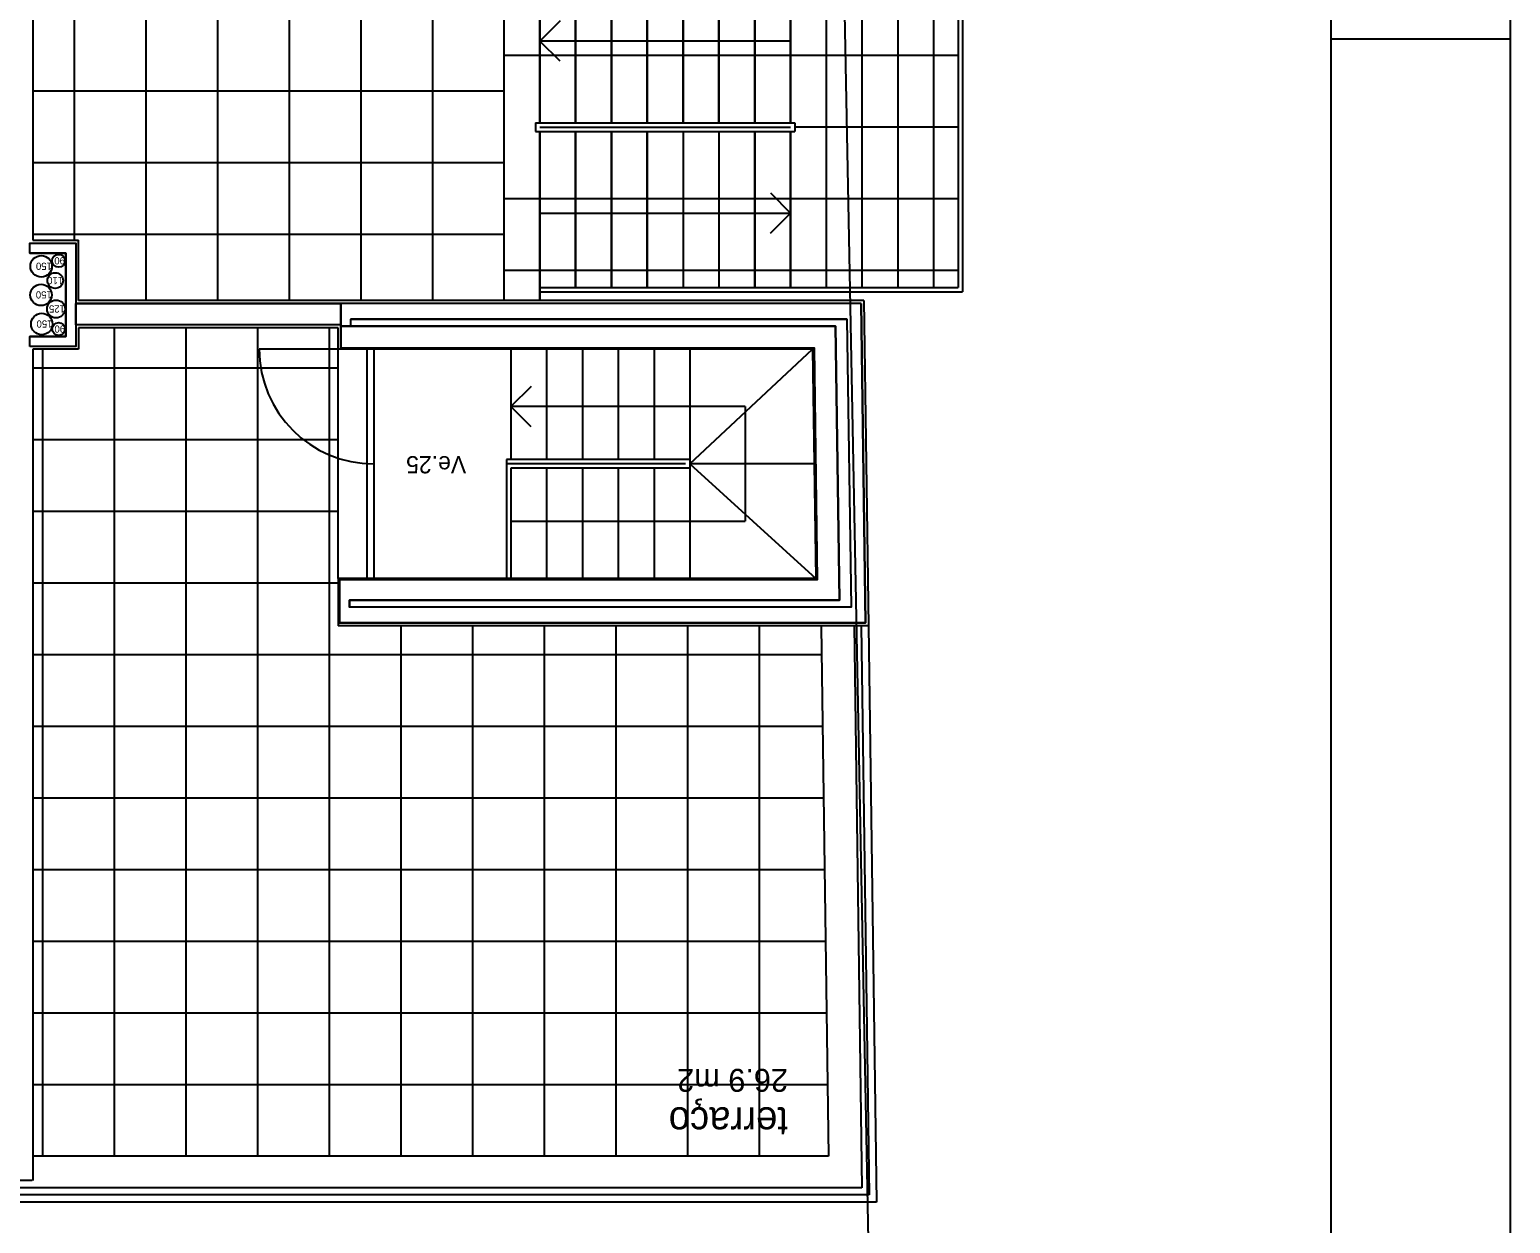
# Model space of a CAD drawing. Extents: x 1278 to 1356, y -253.7 to -224.
# Drawn here: x 1345.63 to 1355.97, y -247.07 to -238.74 of the extents above; entities that cross this region are included whole.
import ezdxf

# ---------------------------------------------------------------- set-up
doc = ezdxf.new("R2010")
doc.units = 0
for name, color, linetype in [('corte', 7, 'Continuous'), ('estereoctomias', 7, 'Continuous'), ('estrutura-eixos', 7, 'Continuous'), ('Level 1', 7, 'Continuous'), ('Level 10', 7, 'Continuous'), ('Level 13', 7, 'Continuous'), ('Level 2', 7, 'Continuous'), ('Level 21', 7, 'Continuous'), ('Level 40', 7, 'Continuous'), ('Level 41', 7, 'Continuous'), ('Level 60', 7, 'Continuous'), ('Level 62', 7, 'Continuous'), ('portas', 7, 'Continuous'), ('revestimentos', 7, 'Continuous')]:
    doc.layers.add(name, color=color, linetype=linetype)

msp = doc.modelspace()

# ---------------------------------------------------------------- linework, layer by layer
at = {"layer": 'corte'}
for p, q in [((1345.634, -240.234), (1345.954, -240.234)), ((1345.954, -240.234), (1345.954, -240.954)), ((1345.634, -240.304), (1345.884, -240.304)), ((1345.884, -240.304), (1345.884, -240.884)), ((1351.435, -240.654), (1345.954, -240.654)), ((1351.435, -240.654), (1351.466, -242.884)), ((1351.336, -240.764), (1347.875, -240.764)), ((1345.884, -240.884), (1345.634, -240.884)), ((1347.805, -240.804), (1345.954, -240.804)), ((1345.954, -240.954), (1345.634, -240.954))]:
    msp.add_line(p, q, dxfattribs=at)
at = {"layer": 'estereoctomias'}
msp.add_line((1348.943, -240.634), (1348.943, -238.206), dxfattribs=at)
for points in [[(1345.634, -240.954), (1345.634, -240.884), (1345.884, -240.884), (1345.884, -240.304), (1345.634, -240.304), (1345.634, -240.234), (1345.954, -240.234), (1345.954, -240.954)], [(1347.805, -240.654), (1347.805, -240.804), (1345.954, -240.804), (1345.954, -240.654)], [(1351.435, -240.654), (1347.805, -240.654), (1347.805, -240.814), (1347.875, -240.814), (1347.875, -240.764), (1351.336, -240.764), (1351.365, -242.774), (1347.865, -242.774), (1347.865, -242.724), (1351.284, -242.724), (1351.257, -240.814), (1347.805, -240.814), (1347.805, -240.964), (1351.107, -240.964), (1351.129, -242.584), (1347.795, -242.584), (1347.795, -242.884), (1351.466, -242.884)]]:
    msp.add_lwpolyline(points, close=True, dxfattribs=at)
at = {"layer": 'estrutura-eixos'}
msp.add_line((1351.148, -229.62), (1351.553, -250.792), dxfattribs=at)
at = {"layer": 'Level 1'}
for p, q in [((1347.805, -240.964), (1347.805, -240.654)), ((1347.875, -240.814), (1347.875, -240.764)), ((1351.336, -240.764), (1351.365, -242.774)), ((1347.875, -240.814), (1351.257, -240.814)), ((1351.257, -240.814), (1351.284, -242.724)), ((1347.805, -240.964), (1351.107, -240.964)), ((1351.107, -240.964), (1351.129, -242.584)), ((1351.129, -242.584), (1347.795, -242.584)), ((1347.795, -242.584), (1347.795, -242.884)), ((1351.284, -242.724), (1347.865, -242.724)), ((1347.865, -242.724), (1347.865, -242.774)), ((1351.352, -242.774), (1347.865, -242.774)), ((1351.365, -242.774), (1351.222, -242.774)), ((1351.466, -242.884), (1347.795, -242.884))]:
    msp.add_line(p, q, dxfattribs=at)
at = {"layer": 'Level 10'}
for p, q in [((1348.943, -240.624), (1348.943, -238.224)), ((1349.193, -239.394), (1349.193, -238.224)), ((1349.443, -239.394), (1349.443, -238.304)), ((1349.693, -239.394), (1349.693, -238.304)), ((1349.943, -239.394), (1349.943, -238.304)), ((1350.193, -239.394), (1350.193, -238.304)), ((1350.443, -239.394), (1350.443, -238.304)), ((1350.693, -239.394), (1350.693, -238.304)), ((1350.943, -239.394), (1350.943, -238.304)), ((1351.193, -240.544), (1351.193, -238.304)), ((1351.443, -240.544), (1351.443, -238.304)), ((1351.693, -240.544), (1351.693, -238.304)), ((1351.943, -240.544), (1351.943, -238.304)), ((1352.113, -238.924), (1348.943, -238.924)), ((1352.113, -239.424), (1350.973, -239.424)), ((1349.193, -240.624), (1349.193, -239.454)), ((1349.443, -240.544), (1349.443, -239.454)), ((1349.693, -240.544), (1349.693, -239.454)), ((1349.943, -240.544), (1349.943, -239.454)), ((1350.693, -240.544), (1350.693, -239.454)), ((1350.943, -240.544), (1350.943, -239.454)), ((1352.113, -239.924), (1348.943, -239.924)), ((1352.113, -240.424), (1348.943, -240.424))]:
    msp.add_line(p, q, dxfattribs=at)
at = {"layer": 'Level 13'}
for p, q in [((1347.985, -240.974), (1347.985, -242.574)), ((1348.035, -240.974), (1348.035, -242.574))]:
    msp.add_line(p, q, dxfattribs=at)
msp.add_arc((1348.035, -240.974), 0.8, 180, 270, dxfattribs=at)
at = {"layer": 'Level 2'}
for p, q in [((1349.193, -238.224), (1349.193, -239.394)), ((1349.443, -238.304), (1349.443, -239.394)), ((1349.693, -238.304), (1349.693, -239.394)), ((1349.943, -238.304), (1349.943, -239.394)), ((1350.193, -238.304), (1350.193, -239.394)), ((1350.443, -238.304), (1350.443, -239.394)), ((1350.693, -238.304), (1350.693, -239.394)), ((1350.943, -238.304), (1350.943, -239.394)), ((1352.113, -238.304), (1352.113, -240.544)), ((1352.143, -238.274), (1352.143, -240.574)), ((1349.335, -238.683), (1349.193, -238.824)), ((1350.943, -238.824), (1349.193, -238.824)), ((1349.335, -238.965), (1349.193, -238.824)), ((1349.163, -239.394), (1350.973, -239.394)), ((1349.163, -239.394), (1349.163, -239.454)), ((1349.193, -239.424), (1350.943, -239.424)), ((1350.973, -239.394), (1350.973, -239.454)), ((1349.163, -239.454), (1350.973, -239.454)), ((1349.193, -239.454), (1349.193, -240.574)), ((1349.443, -239.454), (1349.443, -240.544)), ((1349.693, -239.454), (1349.693, -240.544)), ((1349.943, -239.454), (1349.943, -240.544)), ((1350.193, -239.454), (1350.193, -240.544)), ((1350.443, -239.454), (1350.443, -240.544)), ((1350.693, -239.454), (1350.693, -240.544)), ((1350.943, -239.454), (1350.943, -240.544)), ((1350.802, -239.883), (1350.943, -240.024)), ((1349.193, -240.024), (1350.943, -240.024)), ((1350.802, -240.165), (1350.943, -240.024)), ((1349.193, -240.544), (1352.113, -240.544)), ((1349.193, -240.574), (1349.193, -240.624)), ((1349.193, -240.574), (1352.143, -240.574)), ((1347.785, -242.574), (1347.785, -240.974)), ((1348.99, -240.974), (1348.99, -241.744)), ((1349.24, -240.974), (1349.24, -241.744)), ((1349.49, -240.974), (1349.49, -241.744)), ((1349.74, -240.974), (1349.74, -241.744)), ((1349.99, -240.974), (1349.99, -241.744)), ((1350.24, -240.974), (1350.24, -241.744)), ((1350.24, -241.774), (1351.097, -240.974)), ((1349.132, -241.233), (1348.99, -241.374)), ((1350.627, -241.374), (1348.99, -241.374)), ((1349.132, -241.515), (1348.99, -241.374)), ((1350.627, -241.374), (1350.627, -242.174)), ((1348.96, -241.744), (1348.96, -242.574)), ((1350.24, -241.744), (1348.96, -241.744)), ((1350.21, -241.774), (1348.96, -241.774)), ((1350.24, -241.804), (1348.99, -241.804)), ((1348.99, -241.804), (1348.99, -242.574)), ((1348.99, -241.804), (1348.99, -242.574)), ((1349.24, -241.804), (1349.24, -242.574)), ((1349.49, -241.804), (1349.49, -242.574)), ((1349.74, -241.804), (1349.74, -242.574)), ((1349.99, -241.804), (1349.99, -242.574)), ((1350.24, -241.744), (1350.24, -241.804)), ((1351.108, -241.774), (1350.24, -241.774)), ((1350.24, -241.774), (1351.119, -242.574)), ((1350.24, -241.804), (1350.24, -242.574)), ((1348.99, -242.174), (1350.627, -242.174)), ((1351.156, -242.908), (1351.207, -246.604)), ((1351.386, -242.904), (1351.441, -246.824)), ((1351.436, -242.904), (1351.492, -246.874)), ((1351.486, -242.904), (1351.543, -246.924)), ((1351.207, -246.604), (1345.654, -246.604)), ((1351.441, -246.824), (1345.493, -246.824)), ((1351.492, -246.874), (1345.493, -246.874)), ((1351.543, -246.924), (1345.493, -246.924))]:
    msp.add_line(p, q, dxfattribs=at)
at = {"layer": 'Level 21'}
for p, q in [((1346.443, -238.206), (1346.443, -240.624)), ((1346.943, -238.206), (1346.943, -240.624)), ((1347.443, -238.206), (1347.443, -240.624)), ((1347.943, -238.206), (1347.943, -240.624)), ((1348.443, -238.206), (1348.443, -240.624)), ((1345.943, -238.634), (1345.943, -240.214)), ((1348.943, -239.174), (1345.654, -239.174)), ((1348.943, -239.674), (1345.654, -239.674)), ((1348.943, -240.174), (1345.654, -240.174)), ((1346.223, -240.824), (1346.223, -246.604)), ((1346.723, -240.824), (1346.723, -246.604)), ((1347.223, -240.824), (1347.223, -246.604)), ((1347.723, -240.824), (1347.723, -246.604)), ((1345.723, -240.974), (1345.723, -246.604)), ((1345.654, -241.104), (1347.785, -241.104)), ((1345.654, -241.604), (1347.785, -241.604)), ((1345.654, -242.104), (1347.785, -242.104)), ((1345.654, -242.604), (1347.785, -242.604)), ((1348.223, -242.904), (1348.223, -246.604)), ((1348.723, -242.904), (1348.723, -246.604)), ((1349.223, -242.904), (1349.223, -246.604)), ((1349.723, -242.904), (1349.723, -246.604)), ((1350.223, -242.904), (1350.223, -246.604)), ((1350.723, -242.904), (1350.723, -246.604)), ((1345.654, -243.104), (1351.158, -243.104)), ((1345.654, -243.604), (1351.165, -243.604)), ((1345.654, -244.104), (1351.172, -244.104)), ((1345.654, -244.604), (1351.179, -244.604)), ((1345.654, -245.104), (1351.186, -245.104)), ((1345.654, -245.604), (1351.193, -245.604)), ((1345.654, -246.104), (1351.2, -246.104))]:
    msp.add_line(p, q, dxfattribs=at)
at = {"layer": 'Level 41'}
for centre, radius in [((1345.713, -240.395), 0.075), ((1345.834, -240.357), 0.045), ((1345.811, -240.495), 0.055), ((1345.712, -240.595), 0.075), ((1345.817, -240.693), 0.0625), ((1345.717, -240.798), 0.075), ((1345.835, -240.833), 0.045)]:
    msp.add_circle(centre, radius, dxfattribs=at)
at = {"layer": 'Level 62'}
for p, q in [((1354.716, -253.659), (1354.716, -223.959)), ((1354.716, -238.809), (1355.966, -238.809))]:
    msp.add_line(p, q, dxfattribs=at)
msp.add_lwpolyline([(1355.966, -223.959), (1355.966, -253.659), (1278.016, -253.659), (1278.016, -223.959)], close=True, dxfattribs=at)
at = {"layer": 'portas'}
msp.add_line((1347.785, -240.974), (1347.235, -240.974), dxfattribs=at)
at = {"layer": 'revestimentos'}
for p, q in [((1345.654, -238.634), (1345.654, -240.214)), ((1345.654, -240.214), (1345.974, -240.214)), ((1345.974, -240.634), (1345.974, -240.214)), ((1351.455, -240.634), (1345.974, -240.634)), ((1351.455, -240.634), (1351.486, -242.904)), ((1347.785, -240.824), (1345.974, -240.824)), ((1345.974, -240.824), (1345.974, -240.974)), ((1347.785, -240.974), (1347.785, -240.824)), ((1345.654, -240.974), (1345.654, -246.774)), ((1345.974, -240.974), (1345.654, -240.974)), ((1351.097, -240.974), (1347.785, -240.974)), ((1351.097, -240.974), (1351.119, -242.574)), ((1351.119, -242.574), (1347.785, -242.574)), ((1347.785, -242.574), (1347.785, -242.904)), ((1351.486, -242.904), (1347.785, -242.904)), ((1345.651, -246.774), (1345.461, -246.774))]:
    msp.add_line(p, q, dxfattribs=at)

# ---------------------------------------------------------------- texts
at = {"layer": 'Level 40'}
msp.add_text('Ve.25', height=0.12, rotation=180, dxfattribs=at).set_placement((1348.679, -241.72))
at = {"layer": 'Level 41'}
for s, p in [('150', (1345.788, -240.37)), ('90', (1345.879, -240.332)), ('110', (1345.866, -240.47)), ('150', (1345.787, -240.57)), ('125', (1345.879, -240.668)), ('150', (1345.792, -240.773)), ('90', (1345.88, -240.808))]:
    msp.add_text(s, height=0.05, rotation=180, dxfattribs=at).set_placement(p)
at = {"layer": 'Level 60'}
for s, height, p in [('26.9 m2', 0.16, (1350.925, -245.995)), ('terraço', 0.2, (1350.925, -246.263))]:
    msp.add_text(s, height=height, rotation=180, dxfattribs=at).set_placement(p)

doc.saveas('drawing.dxf')
